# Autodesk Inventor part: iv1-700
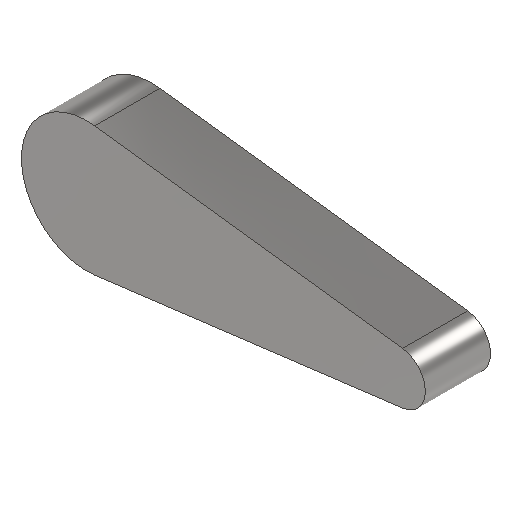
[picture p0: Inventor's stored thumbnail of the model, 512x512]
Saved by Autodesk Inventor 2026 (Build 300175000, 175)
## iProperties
Created: 2022-01
Part Number: iv1-700
Material: Steel, Mild
Document SubType Name: Modeling
Designer: Lars Bertram Pedersen
Density: 7.85 g/cm^3
Appearance: Semi-Polished
Mass: 1054.19 g
Surface Area: 195.392 cm^2
Volume: 134.292 cm^3
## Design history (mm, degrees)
sketch "Sketch1"
  geometry: L1 (3.125, 24.804)-(121.25, 9.922); L2 (3.125, -24.804)-(121.25, -9.922); A1 r 25 centre (0, 0) between (3.125, 24.804) and (3.125, -24.804); A2 r 10 centre (120, 0) between (121.25, -9.922) and (121.25, 9.922); 1 further point
  constraints: 4 end point, 4 point on circle, 4 tangent, 2 centre point, 1 coincident, 1 horizontal alignment
  dimensions: "d0" = 10 radius of A2; "d1" = 25 radius of A1; "d2" = 120 distance of A2.centre point (0, 0)
extrude "Extrusion1" new body sketch "Sketch1" distance "d3" = 25; taper "d4" = 0 deg
body "Solid1"
